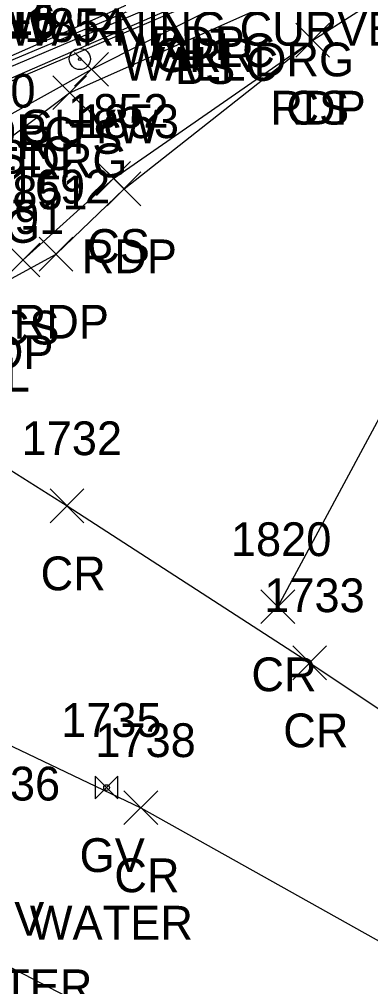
# Model space of a CAD drawing. Extents: x 1657482 to 1661439, y 647981 to 649041.
# Drawn here: x 1659948.1 to 1659969, y 648047.4 to 648104.7 of the extents above; entities that cross this region are included whole.
import ezdxf

# ---------------------------------------------------------------- set-up
doc = ezdxf.new("R2010")
doc.units = 0
for name, color, linetype in [('C_A', 7, 'Continuous'), ('L_A', 7, 'Continuous'), ('L_I', 7, 'Continuous'), ('L_TIC', 7, 'Continuous'), ('LELB', 7, 'Continuous'), ('LW', 7, 'Continuous'), ('P_A', 7, 'Continuous'), ('P_I', 7, 'Continuous'), ('P_TIC', 7, 'Continuous'), ('PET', 7, 'Continuous'), ('PRC', 7, 'Continuous'), ('R_A', 7, 'Continuous'), ('R_I', 7, 'Continuous'), ('R_TIC', 7, 'Continuous'), ('RDG', 7, 'Continuous'), ('RGR', 7, 'Continuous'), ('S_C', 7, 'Continuous'), ('U_A', 7, 'Continuous'), ('U_C', 7, 'Continuous'), ('U_I', 7, 'Continuous'), ('UPGW', 7, 'Continuous'), ('UWV', 7, 'Continuous')]:
    doc.layers.add(name, color=color, linetype=linetype)

msp = doc.modelspace()

# ---------------------------------------------------------------- linework, layer by layer
at = {"layer": 'L_TIC'}
for points in [[(1659964.527, 648102.437), (1659966.527, 648104.437)], [(1659966.527, 648102.437), (1659964.527, 648104.437)], [(1659951.425, 648100.706), (1659953.425, 648102.706)], [(1659953.425, 648100.706), (1659951.425, 648102.706)], [(1659952.726, 648094.247), (1659954.726, 648096.247)], [(1659954.726, 648094.247), (1659952.726, 648096.247)], [(1659947.373, 648089.421), (1659949.373, 648091.421)], [(1659949.373, 648089.421), (1659947.373, 648091.421)]]:
    msp.add_lwpolyline(points, dxfattribs=at)
at = {"layer": 'LELB'}
for points in [[(1659986.305, 648120.95), (1659985.172, 648118.997), (1659979.834, 648115.284), (1659972.354, 648111.752), (1659952.425, 648101.706), (1659944.177, 648097.111), (1659941.553, 648091.094)], [(1659941.563, 648090.011), (1659932.825, 648094.181), (1659931.212, 648094.992), (1659935.607, 648096.348), (1659946.529, 648100.532), (1659958.93, 648105.84), (1659973.072, 648112.969), (1659982.3, 648118.095)], [(1659948.373, 648090.421), (1659953.726, 648095.247), (1659965.527, 648103.437)]]:
    msp.add_lwpolyline(points, dxfattribs=at)
at = {"layer": 'LW'}
for points in [[(1659941.286, 648090.013), (1659940.99, 648089.386), (1659930.702, 648094.209), (1659928.279, 648095.139), (1659928.276, 648095.282), (1659930.501, 648095.819), (1659935.416, 648097.611), (1659946.777, 648101.881), (1659958.528, 648106.836), (1659972.638, 648113.994), (1659985.018, 648121.317)], [(1659941.286, 648090.013), (1659930.836, 648095.132), (1659935.508, 648096.624), (1659946.638, 648100.742), (1659958.73, 648106.028), (1659972.984, 648113.291), (1659985.568, 648120.441), (1659985.018, 648121.317)]]:
    msp.add_lwpolyline(points, dxfattribs=at)
at = {"layer": 'P_TIC'}
for points in [[(1659964.527, 648102.437), (1659966.527, 648104.437)], [(1659966.527, 648102.437), (1659964.527, 648104.437)], [(1659953.348, 648093.635), (1659955.348, 648095.635)], [(1659955.348, 648093.635), (1659953.348, 648095.635)], [(1659949.322, 648089.765), (1659951.322, 648091.765)], [(1659951.322, 648089.765), (1659949.322, 648091.765)], [(1659949.975, 648074.865), (1659951.975, 648076.865)], [(1659951.975, 648074.865), (1659949.975, 648076.865)], [(1659962.459, 648068.889), (1659964.459, 648070.889)], [(1659964.459, 648068.889), (1659962.459, 648070.889)], [(1659964.344, 648065.57), (1659966.344, 648067.57)], [(1659966.344, 648065.57), (1659964.344, 648067.57)], [(1659954.342, 648056.99), (1659956.342, 648058.99)], [(1659956.342, 648056.99), (1659954.342, 648058.99)]]:
    msp.add_lwpolyline(points, dxfattribs=at)
at = {"layer": 'PET'}
for points in [[(1659799.28, 648086.136), (1659822.829, 648084.094), (1659841.236, 648083.238), (1659849.285, 648082.699), (1659853.297, 648081.633), (1659863.28, 648081.701), (1659871.418, 648082.62), (1659885.552, 648085.022), (1659891.684, 648086.345), (1659901.533, 648088.7), (1659915.482, 648092.509), (1659918.893, 648092.262), (1659919.908, 648093.139), (1659925.791, 648090.399), (1659928.096, 648095.554), (1659935.247, 648097.751), (1659946.62, 648102.053), (1659958.358, 648107.252), (1659972.375, 648114.357), (1659985.018, 648121.317), (1659986.135, 648122.233), (1660002.916, 648130.398), (1660023.122, 648141.511)], [(1659863.28, 648081.701), (1659868.598, 648080.447), (1659876.948, 648078.161), (1659883.344, 648076.024), (1659889.16, 648073.962), (1659894.185, 648071.763), (1659897.898, 648070.646), (1659905.34, 648067.906), (1659912.798, 648065.014), (1659924.735, 648059.408), (1659938.824, 648053.114), (1659959.475, 648042.397), (1659969.15, 648037.003), (1659978.866, 648031.627), (1659984.71, 648040.852), (1659990.854, 648049.845), (1659987.428, 648053.134), (1659983.709, 648058.695), (1659981.789, 648065.569), (1659981.786, 648070.317), (1659983.864, 648077.674), (1659998.695, 648097.495), (1660020.131, 648123.934)], [(1659918.893, 648092.262), (1659926.687, 648088.418), (1659938.953, 648083.445), (1659939.381, 648084.566), (1659940.975, 648089.092), (1659941.563, 648090.011), (1659947.038, 648088.96), (1659950.322, 648090.765), (1659954.348, 648094.635), (1659965.527, 648103.437), (1659976.988, 648110.733), (1659982.362, 648114.995), (1659987.705, 648119.209), (1659987.831, 648121.168), (1659986.135, 648122.233)]]:
    msp.add_lwpolyline(points, dxfattribs=at)
at = {"layer": 'PRC'}
for points in [[(1659963.459, 648069.889), (1659971.311, 648084.482), (1659988.169, 648103.589), (1660012.915, 648129.083), (1660023.122, 648141.511)], [(1659891.684, 648086.345), (1659903.341, 648081.608), (1659918.7, 648074.839), (1659936.602, 648066.916), (1659955.342, 648057.99), (1659973.585, 648047.782), (1659984.71, 648040.852)], [(1659938.953, 648083.445), (1659950.975, 648075.865), (1659965.344, 648066.57), (1659986.94, 648052.146)]]:
    msp.add_lwpolyline(points, dxfattribs=at)
at = {"layer": 'R_TIC'}
for points in [[(1659950.126, 648099.323), (1659952.126, 648101.323)], [(1659952.126, 648099.323), (1659950.126, 648101.323)]]:
    msp.add_lwpolyline(points, dxfattribs=at)
at = {"layer": 'RDG'}
msp.add_lwpolyline([(1659944.082, 648090.155), (1659945.939, 648096.438), (1659951.126, 648100.323), (1659964.546, 648106.291), (1659975.578, 648112.028), (1659982.362, 648114.995)], dxfattribs=at)
at = {"layer": 'RGR'}
msp.add_lwpolyline([(1659931.702, 648096.032), (1659946.527, 648101.393), (1659958.619, 648106.542), (1659972.897, 648113.712), (1659985.391, 648120.585)], dxfattribs=at)
at = {"layer": 'UPGW'}
for radius in [0.625, 0.0833]:
    msp.add_circle((1659951.734, 648102.318), radius, dxfattribs=at)
at = {"layer": 'UWV'}
for p, q in [((1659952.65, 648059.851), (1659953.983, 648058.518)), ((1659953.983, 648059.851), (1659952.65, 648058.518))]:
    msp.add_line(p, q, dxfattribs=at)
for points in [[(1659952.65, 648059.851), (1659952.65, 648058.518)], [(1659953.983, 648058.518), (1659953.983, 648059.851)]]:
    msp.add_lwpolyline(points, dxfattribs=at)
msp.add_circle((1659953.317, 648059.185), 0.167, dxfattribs=at)

# ---------------------------------------------------------------- texts
at = {"layer": 'C_A'}
msp.add_text('HVCTRL', height=2, dxfattribs=at).set_placement((1659938.074, 648082.634))
at = {"layer": 'L_A'}
for s, p in [('WALLC', (1659954.063, 648101.836)), ('WALLC', (1659954.266, 648101.028)), ('BS', (1659957.371, 648100.84)), ('CS', (1659963.968, 648098.437)), ('WALLC', (1659942.313, 648096.881)), ('TS', (1659950.835, 648096.706)), ('WALLC', (1659942.174, 648095.742)), ('BS', (1659944.97, 648095.532)), ('CS', (1659952.167, 648090.247)), ('CS', (1659946.814, 648085.421))]:
    msp.add_text(s, height=2, dxfattribs=at).set_placement(p)
at = {"layer": 'L_I'}
for s, p in [('1716', (1659944.348, 648103.532)), ('1715', (1659944.513, 648103.742)), ('1852', (1659951.034, 648098.247)), ('1851', (1659946.247, 648093.421))]:
    msp.add_text(s, height=2, dxfattribs=at).set_placement(p)
at = {"layer": 'P_A'}
for s, p in [('RDP', (1659955.846, 648102.252)), ('RDP', (1659963.015, 648098.437)), ('RDP', (1659944.108, 648097.053)), ('RDP', (1659951.836, 648089.635)), ('RDP', (1659947.81, 648085.765)), ('RDP', (1659944.526, 648083.96)), ('CR', (1659949.408, 648070.865)), ('CR', (1659961.892, 648064.889)), ('CR', (1659963.777, 648061.57)), ('CR', (1659953.775, 648052.99))]:
    msp.add_text(s, height=2, dxfattribs=at).set_placement(p)
at = {"layer": 'P_I'}
for s, p in [('1853', (1659951.655, 648097.635)), ('1692', (1659947.582, 648093.765)), ('1691', (1659944.865, 648091.96)), ('1732', (1659948.282, 648078.865)), ('1820', (1659960.679, 648072.889)), ('1733', (1659962.652, 648069.57)), ('1738', (1659952.649, 648060.99))]:
    msp.add_text(s, height=2, dxfattribs=at).set_placement(p)
at = {"layer": 'R_A'}
for s, p in [('GRR', (1659956.107, 648101.542)), ('DRG', (1659962.034, 648101.291)), ('GRR', (1659944.015, 648096.393)), ('DRG', (1659948.614, 648095.323)), ('DRG', (1659943.427, 648091.438))]:
    msp.add_text(s, height=2, dxfattribs=at).set_placement(p)
at = {"layer": 'R_I'}
for s, p in [('1714', (1659944.401, 648104.393)), ('1854', (1659948.434, 648103.323)), ('1850', (1659943.16, 648099.438))]:
    msp.add_text(s, height=2, dxfattribs=at).set_placement(p)
at = {"layer": 'S_C'}
msp.add_text('WARNING CURVE/WINTER PARKING', height=2, dxfattribs=at).set_placement((1659947.525, 648103.111))
at = {"layer": 'U_A'}
for s, p in [('GUYW', (1659948.127, 648097.318)), ('GV', (1659951.718, 648054.185)), ('GV', (1659945.765, 648050.419))]:
    msp.add_text(s, height=2, dxfattribs=at).set_placement(p)
at = {"layer": 'U_C'}
for p in [(1659948.774, 648050.185), (1659942.82, 648046.419)]:
    msp.add_text('WATER', height=2, dxfattribs=at).set_placement(p)
at = {"layer": 'U_I'}
for s, p in [('1735', (1659950.624, 648062.185)), ('1736', (1659944.616, 648058.419))]:
    msp.add_text(s, height=2, dxfattribs=at).set_placement(p)

doc.saveas('drawing.dxf')
